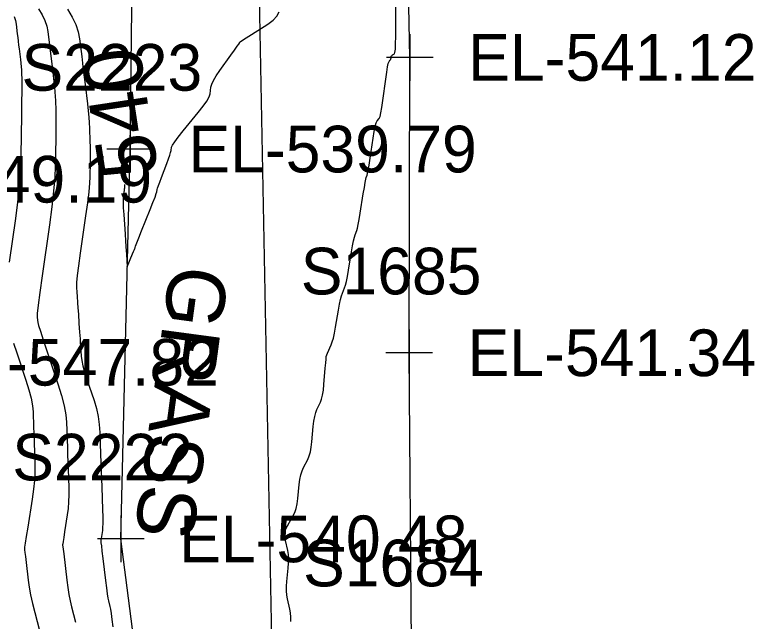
# Model space of a CAD drawing. Extents: x 1724534 to 1727318, y 657156 to 660047.
# Drawn here: x 1725514.8 to 1725578.1, y 658941.3 to 658993.3 of the extents above; entities that cross this region are included whole.
import ezdxf

# ---------------------------------------------------------------- set-up
doc = ezdxf.new("R2010")
doc.units = 0
for name, color, linetype in [('SURVEY - CONTOURS - Index with Text', 7, 'Continuous'), ('SURVEY - CONTOURS - Intermediate with optional Text', 7, 'Continuous'), ('SURVEY - DTM - Breaklines', 7, 'Continuous'), ('SURVEY - DTM - Breaklines - Points - Elevations', 7, 'Continuous'), ('SURVEY - DTM - Breaklines - Points - Locators', 7, 'Continuous'), ('SURVEY - DTM - Breaklines - Points - Numbers', 7, 'Continuous'), ('SURVEY - TRANSPORTATION - Features', 7, 'Continuous'), ('SURVEY - TRANSPORTATION - Features - Points - Elevations', 7, 'Continuous'), ('SURVEY - TRANSPORTATION - Features - Points - Locators', 7, 'Continuous'), ('SURVEY - TRANSPORTATION - Features - Points - Numbers', 7, 'Continuous'), ('SURVEY - UTILITIES - Fiber Optic Cable (Underground) with Text', 7, 'Continuous'), ('SURVEY - VEGETATION - Features - Points - Elevations', 7, 'Continuous'), ('SURVEY - VEGETATION - Features with Text', 7, 'Continuous')]:
    doc.layers.add(name, color=color, linetype=linetype)

msp = doc.modelspace()

# ---------------------------------------------------------------- linework, layer by layer
at = {"layer": 'SURVEY - CONTOURS - Index with Text'}
msp.add_lwpolyline([(1725524.147, 658978.72), (1725524.148, 658978.633), (1725524.146, 658978.484), (1725524.142, 658978.416), (1725524.134, 658978.327), (1725524.12, 658978.216), (1725524.102, 658978.082), (1725524.047, 658977.696), (1725524.034, 658977.491), (1725524.037, 658977.165), (1725524.055, 658976.718), (1725524.09, 658976.15), (1725524.203, 658974.474), (1725524.241, 658973.896), (1725524.274, 658973.416), (1725524.299, 658973.037), (1725524.318, 658972.756), (1725524.39, 658971.681), (1725524.853, 658972.784), (1725524.94, 658972.994), (1725525.004, 658973.149), (1725525.043, 658973.25), (1725525.058, 658973.296), (1725525.066, 658973.348), (1725525.103, 658973.451), (1725525.208, 658973.721), (1725525.381, 658974.157), (1725525.622, 658974.76), (1725526.353, 658976.59), (1725526.595, 658977.2), (1725526.771, 658977.657), (1725526.881, 658977.96), (1725526.925, 658978.111), (1725526.956, 658978.308), (1725526.987, 658978.428), (1725527.058, 658978.641), (1725527.168, 658978.945), (1725527.317, 658979.342), (1725527.769, 658980.524), (1725527.919, 658980.926), (1725528.031, 658981.244), (1725528.105, 658981.48), (1725528.141, 658981.632), (1725528.186, 658981.927), (1725528.26, 658982.098), (1725528.451, 658982.388), (1725528.758, 658982.797), (1725529.18, 658983.325), (1725530.462, 658984.894), (1725530.886, 658985.436), (1725531.197, 658985.884), (1725531.395, 658986.238), (1725531.479, 658986.499), (1725531.554, 658987.071), (1725531.623, 658987.321), (1725531.774, 658987.641), (1725532.007, 658988.031), (1725532.322, 658988.492), (1725533.271, 658989.816), (1725533.583, 658990.252), (1725533.806, 658990.569), (1725533.941, 658990.766), (1725533.987, 658990.844), (1725533.993, 658990.89), (1725534.059, 658990.947), (1725534.256, 658991.082), (1725534.582, 658991.296), (1725535.037, 658991.588), (1725536.425, 658992.472), (1725536.88, 658992.809), (1725537.205, 658993.156), (1725537.401, 658993.513)], dxfattribs=at)
at = {"layer": 'SURVEY - CONTOURS - Intermediate with optional Text'}
for points in [[(1725516.801, 658993.789), (1725517.108, 658993.266), (1725517.342, 658992.767), (1725517.503, 658992.291), (1725517.593, 658991.839), (1725517.734, 658990.665), (1725517.788, 658990.22), (1725517.956, 658988.824), (1725518.111, 658987.543), (1725518.163, 658987.082), (1725518.204, 658986.659), (1725518.232, 658986.275), (1725518.249, 658985.93), (1725518.279, 658985.059), (1725518.287, 658984.664), (1725518.288, 658984.13), (1725518.282, 658983.459), (1725518.27, 658982.649), (1725518.23, 658980.306), (1725518.187, 658979.332), (1725518.089, 658978.17), (1725517.937, 658976.819), (1725517.73, 658975.279), (1725517.104, 658970.921), (1725516.902, 658969.471), (1725516.764, 658968.39), (1725516.69, 658967.679), (1725516.681, 658967.338), (1725516.742, 658966.919), (1725516.806, 658966.649), (1725516.953, 658966.154), (1725517.183, 658965.433), (1725517.496, 658964.487), (1725518.441, 658961.663), (1725518.754, 658960.662), (1725518.983, 658959.778), (1725519.128, 658959.009), (1725519.19, 658958.357), (1725519.264, 658956.176), (1725519.285, 658955.576), (1725519.326, 658954.363), (1725519.381, 658952.735), (1725519.389, 658952.132), (1725519.37, 658951.546), (1725519.325, 658950.977), (1725519.253, 658950.424), (1725519.026, 658948.972), (1725518.952, 658948.495), (1725518.899, 658948.15), (1725518.868, 658947.938), (1725518.859, 658947.86), (1725518.902, 658947.492), (1725518.949, 658947.088), (1725519.216, 658944.824), (1725519.298, 658944.203), (1725519.394, 658943.617), (1725519.503, 658943.067), (1725519.626, 658942.553), (1725519.971, 658941.229)], [(1725519.28, 658993.751), (1725519.677, 658993.072), (1725519.981, 658992.424), (1725520.19, 658991.807), (1725520.306, 658991.221), (1725520.49, 658989.697), (1725520.56, 658989.119), (1725520.631, 658988.528), (1725520.704, 658987.925), (1725520.779, 658987.308), (1725520.979, 658985.646), (1725521.047, 658985.048), (1725521.099, 658984.499), (1725521.136, 658984.001), (1725521.158, 658983.553), (1725521.197, 658982.423), (1725521.208, 658981.994), (1725521.214, 658981.554), (1725521.215, 658981.103), (1725521.209, 658980.641), (1725521.188, 658979.395), (1725521.159, 658978.835), (1725521.089, 658978.091), (1725520.978, 658977.162), (1725520.825, 658976.05), (1725520.364, 658972.836), (1725520.215, 658971.755), (1725520.112, 658970.922), (1725520.056, 658970.338), (1725520.047, 658970.001), (1725520.085, 658969.435), (1725520.099, 658969.219), (1725520.114, 658968.996), (1725520.13, 658968.765), (1725520.146, 658968.526), (1725520.19, 658967.88), (1725520.206, 658967.633), (1725520.223, 658967.377), (1725520.241, 658967.112), (1725520.26, 658966.837), (1725520.31, 658966.093), (1725520.329, 658965.808), (1725520.349, 658965.511), (1725520.37, 658965.203), (1725520.391, 658964.884), (1725520.449, 658964.016), (1725520.497, 658963.647), (1725520.595, 658963.191), (1725520.745, 658962.647), (1725520.945, 658962.015), (1725521.548, 658960.215), (1725521.748, 658959.537), (1725521.898, 658958.854), (1725521.998, 658958.166), (1725522.047, 658957.472), (1725522.11, 658955.616), (1725522.134, 658954.917), (1725522.158, 658954.214), (1725522.182, 658953.506), (1725522.206, 658952.792), (1725522.271, 658950.884), (1725522.288, 658950.235), (1725522.292, 658949.718), (1725522.283, 658949.332), (1725522.261, 658949.079), (1725522.183, 658948.58), (1725522.157, 658948.414), (1725522.14, 658948.292), (1725522.13, 658948.214), (1725522.127, 658948.179), (1725522.131, 658948.145), (1725522.143, 658948.045), (1725522.175, 658947.772), (1725522.228, 658947.325), (1725522.301, 658946.704), (1725522.523, 658944.817), (1725522.602, 658944.176), (1725522.671, 658943.669), (1725522.73, 658943.294), (1725522.781, 658943.053), (1725522.902, 658942.588), (1725522.952, 658942.348), (1725523.012, 658941.975), (1725523.081, 658941.47), (1725523.16, 658940.833)], [(1725538.385, 658941.282), (1725538.385, 658941.669), (1725538.356, 658942.03), (1725538.301, 658942.365), (1725538.116, 658943.226), (1725538.061, 658943.562), (1725538.034, 658943.924), (1725538.035, 658944.314), (1725538.064, 658944.73), (1725538.18, 658945.875), (1725538.209, 658946.291), (1725538.21, 658946.679), (1725538.182, 658947.039), (1725538.126, 658947.371), (1725537.939, 658948.221), (1725537.877, 658948.5), (1725537.833, 658948.701), (1725537.806, 658948.824), (1725537.796, 658948.869), (1725537.792, 658948.885), (1725537.812, 658948.928), (1725537.874, 658949.045), (1725537.979, 658949.236), (1725538.573, 658950.306), (1725538.725, 658950.627), (1725538.847, 658950.986), (1725538.938, 658951.384), (1725538.999, 658951.821), (1725539.119, 658953.037), (1725539.175, 658953.469), (1725539.254, 658953.853), (1725539.356, 658954.189), (1725539.48, 658954.478), (1725539.841, 658955.183), (1725539.965, 658955.477), (1725540.066, 658955.826), (1725540.145, 658956.233), (1725540.201, 658956.697), (1725540.319, 658958.009), (1725540.372, 658958.468), (1725540.441, 658958.863), (1725540.527, 658959.193), (1725540.629, 658959.458), (1725540.922, 658960.078), (1725541.024, 658960.346), (1725541.109, 658960.688), (1725541.178, 658961.102), (1725541.229, 658961.589), (1725541.345, 658962.984), (1725541.383, 658963.442), (1725541.411, 658963.769), (1725541.427, 658963.966), (1725541.433, 658964.036), (1725541.444, 658964.063), (1725541.478, 658964.14), (1725541.534, 658964.268), (1725541.854, 658964.993), (1725541.944, 658965.241), (1725542.036, 658965.576), (1725542.129, 658965.998), (1725542.223, 658966.507), (1725542.477, 658967.979), (1725542.568, 658968.484), (1725542.655, 658968.893), (1725542.735, 658969.207), (1725542.809, 658969.425), (1725543, 658969.88), (1725543.074, 658970.103), (1725543.155, 658970.429), (1725543.242, 658970.859), (1725543.334, 658971.393), (1725543.589, 658972.955), (1725543.68, 658973.485), (1725543.761, 658973.903), (1725543.832, 658974.21), (1725543.892, 658974.405), (1725544.041, 658974.777), (1725544.102, 658974.976), (1725544.173, 658975.294), (1725544.254, 658975.732), (1725544.344, 658976.289), (1725544.6, 658977.932), (1725544.688, 658978.481), (1725544.759, 658978.895), (1725544.813, 658979.175), (1725544.851, 658979.319), (1725544.93, 658979.526), (1725544.968, 658979.674), (1725545.023, 658979.966), (1725545.096, 658980.4), (1725545.185, 658980.977), (1725545.445, 658982.706), (1725545.54, 658983.284), (1725545.627, 658983.721), (1725545.707, 658984.017), (1725545.779, 658984.172), (1725545.964, 658984.398), (1725546.035, 658984.557), (1725546.112, 658984.866), (1725546.194, 658985.324), (1725546.281, 658985.931), (1725546.519, 658987.749), (1725546.602, 658988.353), (1725546.673, 658988.8), (1725546.731, 658989.09), (1725546.777, 658989.223), (1725546.882, 658989.37), (1725546.917, 658989.423), (1725546.944, 658989.473), (1725546.962, 658989.52), (1725546.971, 658989.564), (1725546.984, 658989.675), (1725546.995, 658989.717), (1725547.019, 658989.756), (1725547.056, 658989.795), (1725547.107, 658989.831), (1725547.257, 658989.927), (1725547.307, 658990.047), (1725547.343, 658990.335), (1725547.364, 658990.791), (1725547.372, 658991.415), (1725547.375, 658993.924)], [(1725514.703, 658993.109), (1725514.816, 658992.775), (1725514.879, 658992.458), (1725514.978, 658991.633), (1725515.016, 658991.32), (1725515.055, 658991), (1725515.094, 658990.673), (1725515.134, 658990.34), (1725515.243, 658989.44), (1725515.28, 658989.116), (1725515.308, 658988.82), (1725515.328, 658988.55), (1725515.34, 658988.307), (1725515.361, 658987.696), (1725515.365, 658987.334), (1725515.361, 658986.707), (1725515.35, 658985.814), (1725515.331, 658984.657), (1725515.272, 658981.217), (1725515.227, 658979.912), (1725515.137, 658978.578), (1725515.002, 658977.215), (1725514.823, 658975.822), (1725514.284, 658972.07)], [(1725514.665, 658965.146), (1725514.931, 658964.319), (1725515.713, 658961.98), (1725515.972, 658961.151), (1725516.162, 658960.418), (1725516.283, 658959.782), (1725516.334, 658959.242), (1725516.378, 658957.929), (1725516.395, 658957.435), (1725516.412, 658956.938), (1725516.429, 658956.438), (1725516.446, 658955.933), (1725516.492, 658954.585), (1725516.489, 658954.029), (1725516.447, 658953.375), (1725516.366, 658952.622), (1725516.245, 658951.77), (1725515.869, 658949.365), (1725515.746, 658948.575), (1725515.658, 658948.007), (1725515.606, 658947.663), (1725515.59, 658947.541), (1725515.593, 658947.513), (1725515.602, 658947.433), (1725515.628, 658947.212), (1725515.671, 658946.852), (1725515.73, 658946.351), (1725515.909, 658944.83), (1725515.994, 658944.229), (1725516.116, 658943.565), (1725516.275, 658942.84), (1725516.47, 658942.052), (1725517.04, 658939.869)]]:
    msp.add_lwpolyline(points, dxfattribs=at)
at = {"layer": 'SURVEY - DTM - Breaklines'}
msp.add_lwpolyline([(1725533.454, 658738.584), (1725529.91, 658768.444), (1725528.895, 658798.433), (1725528.35, 658828.444), (1725532.274, 658858.683), (1725531.303, 658888.673), (1725527.687, 658918.53), (1725523.837, 658948.374), (1725524.63, 658981.767), (1725524.814, 658996.206), (1725524.72, 658997.154)], dxfattribs=at)
at = {"layer": 'SURVEY - DTM - Breaklines - Points - Locators'}
for p, q in [((1725524.63, 658983.767), (1725524.63, 658979.767)), ((1725526.63, 658981.767), (1725522.63, 658981.767)), ((1725523.837, 658950.374), (1725523.837, 658946.374)), ((1725525.837, 658948.374), (1725521.837, 658948.374))]:
    msp.add_line(p, q, dxfattribs=at)
at = {"layer": 'SURVEY - TRANSPORTATION - Features'}
msp.add_lwpolyline([(1725548.733, 658939.305), (1725548.535, 658964.315), (1725548.579, 658989.617), (1725548.091, 659014.622), (1725548.852, 659039.619), (1725549.567, 659064.874), (1725549.301, 659089.91), (1725550.369, 659114.889), (1725551.556, 659139.862), (1725552.642, 659165.042), (1725554.694, 659189.961), (1725556.721, 659214.883), (1725558.747, 659239.804), (1725561.49, 659264.678)], dxfattribs=at)
at = {"layer": 'SURVEY - TRANSPORTATION - Features - Points - Locators'}
for p, q in [((1725548.579, 658991.617), (1725548.579, 658987.617)), ((1725550.579, 658989.617), (1725546.579, 658989.617)), ((1725548.535, 658966.315), (1725548.535, 658962.315)), ((1725550.535, 658964.315), (1725546.535, 658964.315))]:
    msp.add_line(p, q, dxfattribs=at)
at = {"layer": 'SURVEY - UTILITIES - Fiber Optic Cable (Underground) with Text'}
msp.add_line((1725538.949, 658827.551), (1725533.816, 659093.214), dxfattribs=at)

# ---------------------------------------------------------------- texts
at = {"layer": 'SURVEY - CONTOURS - Index with Text'}
msp.add_text('540', height=5, rotation=98.59876, dxfattribs=at).set_placement((1725527.063, 658979.697))
at = {"layer": 'SURVEY - DTM - Breaklines - Points - Elevations'}
for s, p in [('EL-539.79', (1725529.63, 658979.767)), ('EL-540.48', (1725528.837, 658946.374))]:
    msp.add_text(s, height=4, dxfattribs=at).set_placement(p)
at = {"layer": 'SURVEY - DTM - Breaklines - Points - Numbers'}
for s, p in [('S2223', (1725515.342, 658986.767)), ('S2222', (1725514.549, 658953.374))]:
    msp.add_text(s, height=4, dxfattribs=at).set_placement(p)
at = {"layer": 'SURVEY - TRANSPORTATION - Features - Points - Elevations'}
for s, p in [('EL-541.12', (1725553.579, 658987.617)), ('EL-541.34', (1725553.535, 658962.315))]:
    msp.add_text(s, height=4, dxfattribs=at).set_placement(p)
at = {"layer": 'SURVEY - TRANSPORTATION - Features - Points - Numbers'}
for s, p in [('S1685', (1725539.247, 658969.315)), ('S1684', (1725539.445, 658944.305))]:
    msp.add_text(s, height=4, dxfattribs=at).set_placement(p)
at = {"layer": 'SURVEY - VEGETATION - Features - Points - Elevations'}
for s, p in [('EL-549.19', (1725501.834, 658977.183)), ('EL-547.82', (1725507.557, 658961.508))]:
    msp.add_text(s, height=4, dxfattribs=at).set_placement(p)
at = {"layer": 'SURVEY - VEGETATION - Features with Text'}
msp.add_text('GRASS', height=5, rotation=262.35617, dxfattribs=at).set_placement((1725528.126, 658971.974))

doc.saveas('drawing.dxf')
